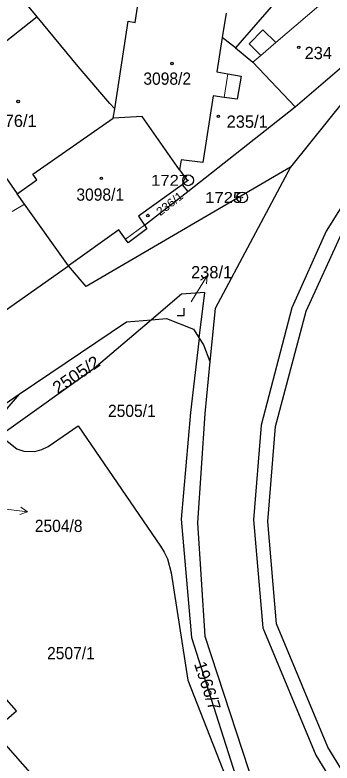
# Model space of a CAD drawing. Extents: x -679733 to -673243, y -1075091 to -1066557.
# Drawn here: x -676225.6 to -676181.6, y -1071918.1 to -1071814.4 of the extents above; entities that cross this region are included whole.
import ezdxf
from ezdxf.enums import TextEntityAlignment as Align

# ---------------------------------------------------------------- set-up
doc = ezdxf.new("R2010")
doc.units = 0
doc.header["$LTSCALE"] = 0.68
for name, color, linetype, lineweight in [('1', 7, 'Continuous', 25), ('3', 7, 'Continuous', 25), ('4', 7, 'Continuous', 13), ('5', 7, 'Continuous', 25), ('7', 7, 'Continuous', 13), ('8', 7, 'Continuous', 25)]:
    doc.layers.add(name, color=color, linetype=linetype, lineweight=lineweight)
doc.layers.add('2', color=7, linetype='Continuous')

msp = doc.modelspace()

# ---------------------------------------------------------------- linework, layer by layer
at = {"layer": '1'}
for p, q in [((-676222.48, -1071814.67), (-676234.84, -1071799.57)), ((-676196.31, -1071814.13), (-676196.84, -1071817.52)), ((-676195.03, -1071818.98), (-676196.84, -1071817.52)), ((-676211.94, -1071828.71), (-676211.74, -1071827.41))]:
    msp.add_line(p, q, dxfattribs=at)
for points in [[(-676099.38, -1071590.43), (-676125.1, -1071603.36), (-676134.03, -1071611.63), (-676132.28, -1071638.9), (-676113.31, -1071708.7), (-676111.17, -1071722.51), (-676112.16, -1071739.84), (-676114.63, -1071749.43), (-676121.41, -1071764.03), (-676135.15, -1071783.33), (-676142.46, -1071792.76), (-676166.36, -1071822.04), (-676175.39, -1071833.12), (-676182.45, -1071844.4), (-676187.2, -1071855.01), (-676191.45, -1071871.27), (-676192.51, -1071884.43), (-676191.2, -1071899.37), (-676183.88, -1071917.06), (-676171.89, -1071936.65), (-676157.14, -1071950.29), (-676143.77, -1071959.8), (-676108.24, -1071982.64), (-676103.47, -1071979.82)], [(-676122.57, -1071748.24), (-676128.67, -1071760.82), (-676139.08, -1071775.3), (-676150.18, -1071791.44), (-676172.35, -1071816.74), (-676187.37, -1071835.51)], [(-676191.23, -1071804.78), (-676187.43, -1071808.44), (-676187.57, -1071810.36), (-676195.03, -1071818.98)], [(-676211.74, -1071827.41), (-676209.86, -1071815.28), (-676208.92, -1071815.43), (-676208.45, -1071812.38)], [(-676222.48, -1071814.67), (-676238.99, -1071827.71), (-676239.13, -1071827.54), (-676240.33, -1071828.53), (-676236.02, -1071834.41)], [(-676211.74, -1071827.41), (-676212.44, -1071826.66), (-676216.81, -1071821.53), (-676222.48, -1071814.67)], [(-676195.03, -1071818.98), (-676192.6, -1071820.94), (-676186.72, -1071827.16), (-676174.13, -1071816.31)], [(-676196.84, -1071817.52), (-676197.59, -1071822.28), (-676196.06, -1071822.57), (-676194.24, -1071822.87), (-676194.79, -1071826.09), (-676196.57, -1071825.86), (-676198.12, -1071825.63), (-676199.53, -1071834.85), (-676202.52, -1071834.51), (-676202.76, -1071835.86)], [(-676202.76, -1071835.86), (-676201.64, -1071837.42), (-676202.42, -1071837.98), (-676201.63, -1071838.86), (-676186.72, -1071827.16)], [(-676225.24, -1071839.2), (-676222.52, -1071837.26), (-676223.08, -1071836.47), (-676211.94, -1071828.71)], [(-676202.76, -1071835.86), (-676207.95, -1071828.5), (-676211.94, -1071828.71)], [(-676236.02, -1071834.41), (-676231.33, -1071830.92), (-676227.7, -1071835.74), (-676225.24, -1071839.2)], [(-676137.35, -1071957.74), (-676142.3, -1071958.36), (-676155.61, -1071948.79), (-676170.23, -1071935.55), (-676182.22, -1071915.93), (-676189.31, -1071898.82), (-676190.52, -1071884.65), (-676189.49, -1071871.47), (-676185.21, -1071855.48), (-676180.3, -1071844.64), (-676174.29, -1071835.37), (-676172.03, -1071834.46)], [(-676187.37, -1071835.51), (-676215.69, -1071852.05), (-676218.13, -1071849.18)], [(-676187.37, -1071835.51), (-676197.84, -1071855.1), (-676198.56, -1071862.46)], [(-676202.42, -1071837.98), (-676208.43, -1071842.29), (-676207.62, -1071843.56), (-676201.63, -1071838.86)], [(-676218.13, -1071849.18), (-676224.22, -1071840.63), (-676225.24, -1071839.2)], [(-676207.62, -1071843.56), (-676207.3, -1071844.06), (-676209.9, -1071845.98), (-676210.25, -1071845.49), (-676211.16, -1071844.21), (-676218.13, -1071849.18)], [(-676231.96, -1071858.9), (-676230.1, -1071857.61), (-676218.13, -1071849.18)], [(-676200.03, -1071859.2), (-676199.28, -1071852.87), (-676202.49, -1071853.11), (-676206.65, -1071856.66)], [(-676206.65, -1071856.66), (-676214.57, -1071863.42), (-676227.08, -1071872.34)], [(-676224.96, -1071866.99), (-676210.13, -1071856.97), (-676206.65, -1071856.66)], [(-676206.65, -1071856.66), (-676204.58, -1071856.48), (-676200.83, -1071857.95), (-676200.03, -1071859.2)], [(-676200.03, -1071859.2), (-676201.25, -1071869.53), (-676202.55, -1071884.32), (-676201.11, -1071900.72), (-676193.28, -1071925.25), (-676186.7, -1071937.9)], [(-676200.03, -1071859.2), (-676199.43, -1071860.14), (-676198.56, -1071862.46)], [(-676198.56, -1071862.46), (-676199.27, -1071869.68), (-676200.26, -1071884.85), (-676199.27, -1071900.55), (-676191.45, -1071924.38), (-676184.56, -1071937.27)], [(-676240.59, -1071878.19), (-676228.46, -1071869.36), (-676224.96, -1071866.99)], [(-676224.96, -1071866.99), (-676226.67, -1071868.98), (-676227.28, -1071870.89), (-676227.08, -1071872.34)], [(-676227.08, -1071872.34), (-676226.86, -1071873.32), (-676225.29, -1071874.56), (-676224.35, -1071874.89), (-676222.83, -1071874.93), (-676221.84, -1071874.67), (-676220.94, -1071874.24), (-676216.81, -1071871.39), (-676205.41, -1071888.05), (-676204.87, -1071888.91), (-676204.42, -1071889.82), (-676203.93, -1071891.77), (-676201.63, -1071906.65), (-676192.52, -1071929.9), (-676184.66, -1071947.23), (-676184.22, -1071948.69), (-676184.11, -1071949.73), (-676184.14, -1071951.2), (-676184.39, -1071952.29), (-676182.49, -1071951.53)], [(-676212.87, -1071956.4), (-676201.2, -1071946.34), (-676200.07, -1071945.3), (-676206.47, -1071938.1), (-676204.7, -1071936.5), (-676205.81, -1071935.25), (-676207.9, -1071937.16), (-676228.58, -1071913.66), (-676225.33, -1071910.89), (-676233.96, -1071901.19), (-676236.8, -1071903.68), (-676241.2, -1071898.74), (-676242.19, -1071899.63), (-676258.77, -1071914.06)]]:
    msp.add_lwpolyline(points, dxfattribs=at)
at = {"layer": '3'}
msp.add_lwpolyline([(-676203.101, -1071856.07), (-676202.1, -1071856.07), (-676202.1, -1071855.07)], dxfattribs=at)
at = {"layer": '4'}
for p, q in [((-676182.04, -1071811.89), (-676189.43, -1071818.22)), ((-676191.2, -1071816.46), (-676193.12, -1071818.4)), ((-676189.43, -1071818.22), (-676191.2, -1071816.46)), ((-676193.12, -1071818.4), (-676191.51, -1071820)), ((-676191.51, -1071820), (-676189.43, -1071818.22)), ((-676191.51, -1071820), (-676192.6, -1071820.94)), ((-676196.57, -1071825.86), (-676196.06, -1071822.57)), ((-676225.97, -1071841.65), (-676224.22, -1071840.63)), ((-676210.25, -1071845.49), (-676207.62, -1071843.56))]:
    msp.add_line(p, q, dxfattribs=at)
at = {"layer": '5'}
for centre in [(-676186.2468, -1071818.8892), (-676203.7968, -1071821.1392), (-676225.1268, -1071826.3992), (-676197.3868, -1071828.4592), (-676213.5868, -1071837.0592), (-676207.1468, -1071842.2192)]:
    msp.add_circle(centre, 0.175, dxfattribs=at)
at = {"layer": '7'}
for p, q in [((-676198.92, -1071850.575), (-676199.875, -1071851.159)), ((-676223.811, -1071883.296), (-676224.744, -1071882.677))]:
    msp.add_line(p, q, dxfattribs=at)
for points in [[(-676201.16, -1071854.16), (-676200.51, -1071853.12), (-676198.92, -1071850.575), (-676199.026, -1071851.69)], [(-676235.63, -1071881.91), (-676226.79, -1071882.93), (-676223.811, -1071883.296), (-676224.866, -1071883.671)]]:
    msp.add_lwpolyline(points, dxfattribs=at)
at = {"layer": '8'}
for centre, radius in [((-676201.57, -1071837.3298), 0.75), ((-676201.57, -1071837.3298), 0.03), ((-676194.08, -1071839.7098), 0.75), ((-676194.08, -1071839.7098), 0.03)]:
    msp.add_circle(centre, radius, dxfattribs=at)

# ---------------------------------------------------------------- texts
at = {"layer": '2'}
for s, p in [('234', (-676183.539, -1071820.529)), ('476/1', (-676225.4, -1071829.93)), ('235/1', (-676193.39, -1071830.04))]:
    msp.add_text(s, height=1.7, dxfattribs=at).set_placement(p, align=Align.CENTER)
at = {"layer": '2', "width": 0.95}
for s, p in [('3098/2', (-676204.469, -1071824.08)), ('3098/1', (-676213.749, -1071840.16)), ('2505/1', (-676209.369, -1071870.15)), ('2507/1', (-676217.809, -1071903.749))]:
    msp.add_text(s, height=1.7, dxfattribs=at).set_placement(p, align=Align.CENTER)
at = {"layer": '2'}
for s, height, rotation, width, p in [('236/1', 1.14, 38, 1.1, (-676203.7849, -1071841.0265)), ('2505/2', 1.7, 34, 1.05, (-676216.6073, -1071864.9906))]:
    msp.add_text(s, height=height, rotation=rotation, dxfattribs=dict(at, width=width)).set_placement(p, align=Align.CENTER)
msp.add_text('238/1', height=1.7, dxfattribs=at).set_placement((-676201.16, -1071850.92))
at = {"layer": '2', "width": 0.95}
msp.add_text('2504/8', height=1.7, dxfattribs=at).set_placement((-676222.81, -1071886.103))
at = {"layer": '2'}
msp.add_text('1966/7', height=1.7, rotation=288, dxfattribs=at).set_placement((-676199.6905, -1071907.6973), align=Align.CENTER)
at = {"layer": '8', "width": 1.15}
for s, p in [('1727', (-676201.569, -1071838.08)), ('1725', (-676194.079, -1071840.46))]:
    msp.add_text(s, height=1.5, dxfattribs=at).set_placement(p, align=Align.RIGHT)

doc.saveas('drawing.dxf')
